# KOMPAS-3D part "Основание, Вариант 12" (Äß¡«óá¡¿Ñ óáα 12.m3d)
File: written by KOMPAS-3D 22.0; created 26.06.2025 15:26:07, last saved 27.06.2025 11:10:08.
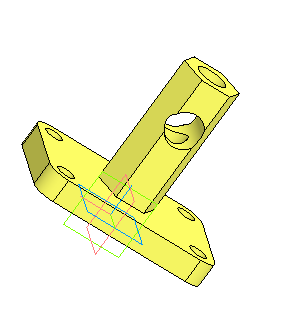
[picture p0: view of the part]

Document properties: Автор: Helen; Полное имя файла: D:\MY\WORK\MPEI\ППЭ_2025-2026\Варианты\Вар 12 СБ\Основание вар 12.m3d

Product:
- Part/product: Основание  | designation Вариант 12
    Масса: 2.98152

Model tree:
1. Эскиз:1
2. Элемент выдавливания:1
     Расстояние 1 = 20
3. Эскиз:3  (with: Элемент выдавливания:1)
4. Элемент выдавливания:3
     Расстояние 2 = 20
5. Массив по сетке:1  (with: Элемент выдавливания:3, Эскиз:3, Элемент выдавливания:1)  (4 pattern instances)
     Шаг 1 = 120; Угол раствора = 90; Шаг 2 = 70
6. Эскиз:4  (with: Элемент выдавливания:1)
7. Элемент выдавливания:4
     Расстояние 1 = 110
8. Эскиз:5  (with: Элемент выдавливания:4)
9. Элемент выдавливания:5
     Расстояние 2 = 130
10. Эскиз:6
11. Элемент выдавливания:6
     Расстояние 1 = 50

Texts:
  Вариант 12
